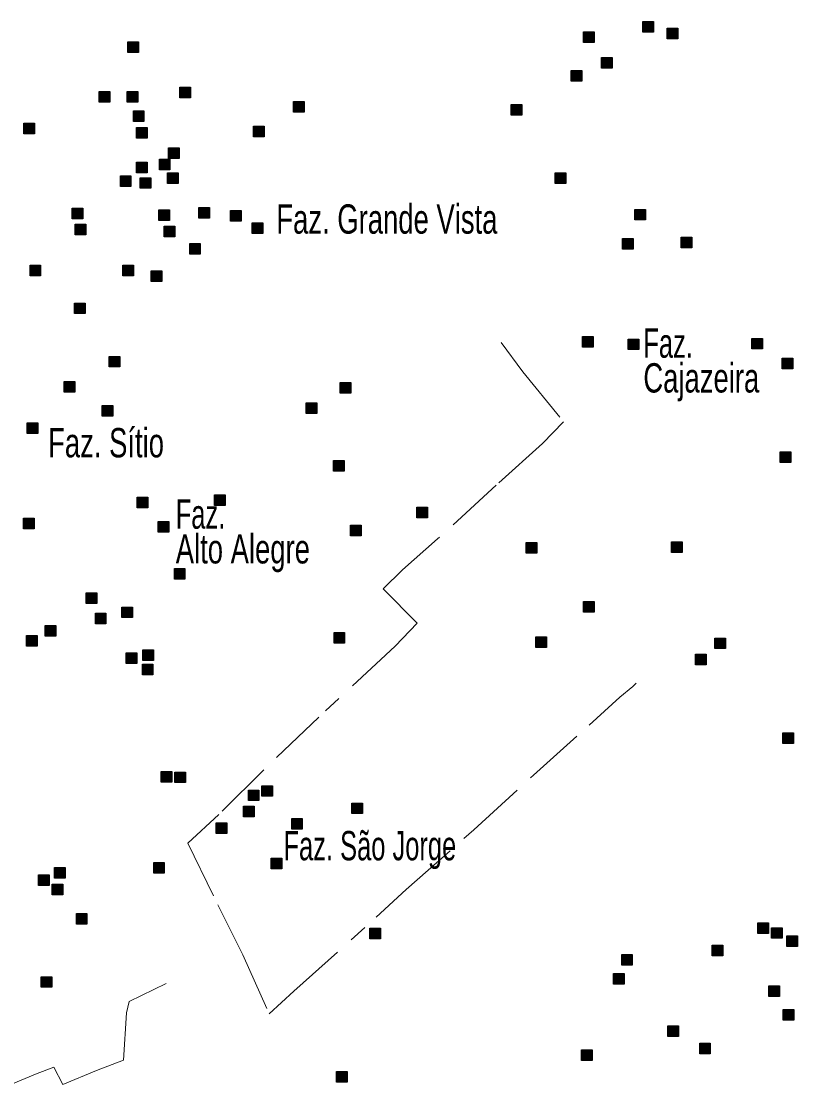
# Model space of a CAD drawing. Extents: x 445.6 to 500, y 8618.1 to 8673.4.
# Drawn here: x 495.76 to 499.99, y 8644.26 to 8650.11 of the extents above; entities that cross this region are included whole.
import ezdxf
from ezdxf.enums import TextEntityAlignment as Align

# ---------------------------------------------------------------- set-up
doc = ezdxf.new("R2010")
doc.units = 0
doc.header["$LTSCALE"] = 0.064
doc.linetypes.add('DOT_DASHED', pattern=[7.7, 5, -1.2, 0.3, -1.2])
doc.layers.add('2', color=7, linetype='Continuous', lineweight=25)
doc.layers.add('22', color=7, linetype='DOT_DASHED', lineweight=13)
doc.layers.add('61', color=7, linetype='Continuous')

msp = doc.modelspace()

# ---------------------------------------------------------------- hatches: boundary and pattern name
at = {"layer": '2'}
for points in [[(499.1475, 8650.1089), (499.2055, 8650.1089), (499.2055, 8650.0509), (499.1475, 8650.0509)], [(498.8232, 8650.0513), (498.8812, 8650.0513), (498.8812, 8649.9933), (498.8232, 8649.9933)], [(499.2792, 8650.0716), (499.3372, 8650.0716), (499.3372, 8650.0136), (499.2792, 8650.0136)], [(496.3356, 8649.9972), (496.3936, 8649.9972), (496.3936, 8649.9392), (496.3356, 8649.9392)], [(498.9211, 8649.9124), (498.9791, 8649.9124), (498.9791, 8649.8544), (498.9211, 8649.8544)], [(498.7556, 8649.8412), (498.8136, 8649.8412), (498.8136, 8649.7832), (498.7556, 8649.7832)], [(496.1802, 8649.7262), (496.2382, 8649.7262), (496.2382, 8649.6682), (496.1802, 8649.6682)], [(496.3322, 8649.7262), (496.3902, 8649.7262), (496.3902, 8649.6682), (496.3322, 8649.6682)], [(496.6194, 8649.7499), (496.6774, 8649.7499), (496.6774, 8649.6919), (496.6194, 8649.6919)], [(497.2409, 8649.672), (497.2989, 8649.672), (497.2989, 8649.614), (497.2409, 8649.614)], [(498.428, 8649.6549), (498.486, 8649.6549), (498.486, 8649.5969), (498.428, 8649.5969)], [(496.366, 8649.6211), (496.424, 8649.6211), (496.424, 8649.5631), (496.366, 8649.5631)], [(495.7681, 8649.5534), (495.8261, 8649.5534), (495.8261, 8649.4954), (495.7681, 8649.4954)], [(496.3829, 8649.5297), (496.4409, 8649.5297), (496.4409, 8649.4717), (496.3829, 8649.4717)], [(497.0213, 8649.5364), (497.0793, 8649.5364), (497.0793, 8649.4784), (497.0213, 8649.4784)], [(496.5586, 8649.4178), (496.6166, 8649.4178), (496.6166, 8649.3598), (496.5586, 8649.3598)], [(496.5079, 8649.3569), (496.5659, 8649.3569), (496.5659, 8649.2989), (496.5079, 8649.2989)], [(496.3829, 8649.3399), (496.4409, 8649.3399), (496.4409, 8649.2819), (496.3829, 8649.2819)], [(496.2951, 8649.2654), (496.3531, 8649.2654), (496.3531, 8649.2074), (496.2951, 8649.2074)], [(496.4032, 8649.2552), (496.4612, 8649.2552), (496.4612, 8649.1972), (496.4032, 8649.1972)], [(496.5518, 8649.2823), (496.6098, 8649.2823), (496.6098, 8649.2243), (496.5518, 8649.2243)], [(498.6678, 8649.2822), (498.7258, 8649.2822), (498.7258, 8649.2242), (498.6678, 8649.2242)], [(496.0316, 8649.0892), (496.0896, 8649.0892), (496.0896, 8649.0312), (496.0316, 8649.0312)], [(496.5045, 8649.079), (496.5625, 8649.079), (496.5625, 8649.021), (496.5045, 8649.021)], [(496.7241, 8649.0926), (496.7821, 8649.0926), (496.7821, 8649.0346), (496.7241, 8649.0346)], [(496.8958, 8649.0756), (496.9538, 8649.0756), (496.9538, 8649.0176), (496.8958, 8649.0176)], [(499.1035, 8649.0823), (499.1615, 8649.0823), (499.1615, 8649.0243), (499.1035, 8649.0243)], [(496.0485, 8649.0011), (496.1065, 8649.0011), (496.1065, 8648.9431), (496.0485, 8648.9431)], [(497.0146, 8649.0079), (497.0726, 8649.0079), (497.0726, 8648.9499), (497.0146, 8648.9499)], [(496.5349, 8648.991), (496.5929, 8648.991), (496.5929, 8648.933), (496.5349, 8648.933)], [(496.6734, 8648.8961), (496.7314, 8648.8961), (496.7314, 8648.8381), (496.6734, 8648.8381)], [(499.036, 8648.9231), (499.094, 8648.9231), (499.094, 8648.8651), (499.036, 8648.8651)], [(499.3569, 8648.9299), (499.4149, 8648.9299), (499.4149, 8648.8719), (499.3569, 8648.8719)], [(495.8019, 8648.7775), (495.8599, 8648.7775), (495.8599, 8648.7195), (495.8019, 8648.7195)], [(496.3086, 8648.7775), (496.3666, 8648.7775), (496.3666, 8648.7195), (496.3086, 8648.7195)], [(496.464, 8648.747), (496.522, 8648.747), (496.522, 8648.689), (496.464, 8648.689)], [(496.0451, 8648.5708), (496.1031, 8648.5708), (496.1031, 8648.5128), (496.0451, 8648.5128)], [(498.8172, 8648.3876), (498.8752, 8648.3876), (498.8752, 8648.3296), (498.8172, 8648.3296)], [(499.0664, 8648.3742), (499.1244, 8648.3742), (499.1244, 8648.3162), (499.0664, 8648.3162)], [(499.7419, 8648.3776), (499.7999, 8648.3776), (499.7999, 8648.3196), (499.7419, 8648.3196)], [(496.2343, 8648.2795), (496.2923, 8648.2795), (496.2923, 8648.2215), (496.2343, 8648.2215)], [(499.9075, 8648.2692), (499.9655, 8648.2692), (499.9655, 8648.2112), (499.9075, 8648.2112)], [(495.9887, 8648.1416), (496.0467, 8648.1416), (496.0467, 8648.0836), (495.9887, 8648.0836)], [(497.4951, 8648.1366), (497.5531, 8648.1366), (497.5531, 8648.0786), (497.4951, 8648.0786)], [(496.1956, 8648.0114), (496.2536, 8648.0114), (496.2536, 8647.9534), (496.1956, 8647.9534)], [(497.3093, 8648.0248), (497.3673, 8648.0248), (497.3673, 8647.9668), (497.3093, 8647.9668)], [(495.7869, 8647.9165), (495.8449, 8647.9165), (495.8449, 8647.8585), (495.7869, 8647.8585)], [(497.4579, 8647.7098), (497.5159, 8647.7098), (497.5159, 8647.6518), (497.4579, 8647.6518)], [(499.8969, 8647.7573), (499.9549, 8647.7573), (499.9549, 8647.6993), (499.8969, 8647.6993)], [(496.3872, 8647.5099), (496.4452, 8647.5099), (496.4452, 8647.4519), (496.3872, 8647.4519)], [(496.8085, 8647.5225), (496.8665, 8647.5225), (496.8665, 8647.4645), (496.8085, 8647.4645)], [(497.9133, 8647.4555), (497.9713, 8647.4555), (497.9713, 8647.3975), (497.9133, 8647.3975)], [(495.7667, 8647.3947), (495.8247, 8647.3947), (495.8247, 8647.3367), (495.7667, 8647.3367)], [(496.502, 8647.3777), (496.56, 8647.3777), (496.56, 8647.3197), (496.502, 8647.3197)], [(497.5518, 8647.3573), (497.6098, 8647.3573), (497.6098, 8647.2993), (497.5518, 8647.2993)], [(498.5094, 8647.2627), (498.5674, 8647.2627), (498.5674, 8647.2047), (498.5094, 8647.2047)], [(499.3032, 8647.2661), (499.3612, 8647.2661), (499.3612, 8647.2081), (499.3032, 8647.2081)], [(496.5898, 8647.1202), (496.6478, 8647.1202), (496.6478, 8647.0622), (496.5898, 8647.0622)], [(496.1078, 8646.9882), (496.1658, 8646.9882), (496.1658, 8646.9302), (496.1078, 8646.9302)], [(496.3037, 8646.9103), (496.3617, 8646.9103), (496.3617, 8646.8523), (496.3037, 8646.8523)], [(498.8235, 8646.9408), (498.8815, 8646.9408), (498.8815, 8646.8828), (498.8235, 8646.8828)], [(496.1585, 8646.8764), (496.2165, 8646.8764), (496.2165, 8646.8184), (496.1585, 8646.8184)], [(495.8849, 8646.8086), (495.9429, 8646.8086), (495.9429, 8646.7506), (495.8849, 8646.7506)], [(497.4613, 8646.7713), (497.5193, 8646.7713), (497.5193, 8646.7133), (497.4613, 8646.7133)], [(495.7836, 8646.7544), (495.8416, 8646.7544), (495.8416, 8646.6964), (495.7836, 8646.6964)], [(498.5634, 8646.7477), (498.6214, 8646.7477), (498.6214, 8646.6897), (498.5634, 8646.6897)], [(499.5396, 8646.7409), (499.5976, 8646.7409), (499.5976, 8646.6829), (499.5396, 8646.6829)], [(496.3274, 8646.6595), (496.3854, 8646.6595), (496.3854, 8646.6015), (496.3274, 8646.6015)], [(496.4186, 8646.6765), (496.4766, 8646.6765), (496.4766, 8646.6185), (496.4186, 8646.6185)], [(499.4349, 8646.6529), (499.4929, 8646.6529), (499.4929, 8646.5949), (499.4349, 8646.5949)], [(496.4152, 8646.5986), (496.4732, 8646.5986), (496.4732, 8646.5406), (496.4152, 8646.5406)], [(499.9104, 8646.2226), (499.9684, 8646.2226), (499.9684, 8646.1646), (499.9104, 8646.1646)], [(496.5175, 8646.0123), (496.5755, 8646.0123), (496.5755, 8645.9543), (496.5175, 8645.9543)], [(496.5918, 8646.0089), (496.6498, 8646.0089), (496.6498, 8645.9509), (496.5918, 8645.9509)], [(496.9938, 8645.9106), (497.0518, 8645.9106), (497.0518, 8645.8526), (496.9938, 8645.8526)], [(497.0681, 8645.9343), (497.1261, 8645.9343), (497.1261, 8645.8763), (497.0681, 8645.8763)], [(497.5582, 8645.8395), (497.6162, 8645.8395), (497.6162, 8645.7815), (497.5582, 8645.7815)], [(496.9668, 8645.8225), (497.0248, 8645.8225), (497.0248, 8645.7645), (496.9668, 8645.7645)], [(496.8181, 8645.7311), (496.8761, 8645.7311), (496.8761, 8645.6731), (496.8181, 8645.6731)], [(497.2302, 8645.7548), (497.2882, 8645.7548), (497.2882, 8645.6968), (497.2302, 8645.6968)], [(495.9365, 8645.4871), (495.9945, 8645.4871), (495.9945, 8645.4291), (495.9365, 8645.4291)], [(496.477, 8645.5142), (496.535, 8645.5142), (496.535, 8645.4562), (496.477, 8645.4562)], [(497.1188, 8645.538), (497.1768, 8645.538), (497.1768, 8645.48), (497.1188, 8645.48)], [(495.8487, 8645.4465), (495.9067, 8645.4465), (495.9067, 8645.3885), (495.8487, 8645.3885)], [(495.923, 8645.3957), (495.981, 8645.3957), (495.981, 8645.3377), (495.923, 8645.3377)], [(496.0548, 8645.2364), (496.1128, 8645.2364), (496.1128, 8645.1784), (496.0548, 8645.1784)], [(497.6568, 8645.1551), (497.7148, 8645.1551), (497.7148, 8645.0971), (497.6568, 8645.0971)], [(499.7746, 8645.1856), (499.8326, 8645.1856), (499.8326, 8645.1276), (499.7746, 8645.1276)], [(499.8489, 8645.1585), (499.9069, 8645.1585), (499.9069, 8645.1005), (499.8489, 8645.1005)], [(499.9334, 8645.1145), (499.9914, 8645.1145), (499.9914, 8645.0565), (499.9334, 8645.0565)], [(499.0315, 8645.0128), (499.0895, 8645.0128), (499.0895, 8644.9548), (499.0315, 8644.9548)], [(499.5247, 8645.0637), (499.5827, 8645.0637), (499.5827, 8645.0057), (499.5247, 8645.0057)], [(498.9876, 8644.9078), (499.0456, 8644.9078), (499.0456, 8644.8498), (498.9876, 8644.8498)], [(495.8622, 8644.8909), (495.9202, 8644.8909), (495.9202, 8644.8329), (495.8622, 8644.8329)], [(499.8349, 8644.8402), (499.8929, 8644.8402), (499.8929, 8644.7822), (499.8349, 8644.7822)], [(499.9127, 8644.7113), (499.9707, 8644.7113), (499.9707, 8644.6533), (499.9127, 8644.6533)], [(499.2837, 8644.6231), (499.3417, 8644.6231), (499.3417, 8644.5651), (499.2837, 8644.5651)], [(498.812, 8644.4911), (498.87, 8644.4911), (498.87, 8644.4331), (498.812, 8644.4331)], [(499.4571, 8644.5284), (499.5151, 8644.5284), (499.5151, 8644.4704), (499.4571, 8644.4704)], [(497.4744, 8644.3725), (497.5324, 8644.3725), (497.5324, 8644.3145), (497.4744, 8644.3145)]]:
    msp.add_hatch(color=256, dxfattribs=at).paths.add_polyline_path(points)

# ---------------------------------------------------------------- linework, layer by layer
for points in [[(499.1475, 8650.1089), (499.2055, 8650.1089), (499.2055, 8650.0509), (499.1475, 8650.0509)], [(498.8232, 8650.0513), (498.8812, 8650.0513), (498.8812, 8649.9933), (498.8232, 8649.9933)], [(499.2792, 8650.0716), (499.3372, 8650.0716), (499.3372, 8650.0136), (499.2792, 8650.0136)], [(496.3356, 8649.9972), (496.3936, 8649.9972), (496.3936, 8649.9392), (496.3356, 8649.9392)], [(498.9211, 8649.9124), (498.9791, 8649.9124), (498.9791, 8649.8544), (498.9211, 8649.8544)], [(498.7556, 8649.8412), (498.8136, 8649.8412), (498.8136, 8649.7832), (498.7556, 8649.7832)], [(496.1802, 8649.7262), (496.2382, 8649.7262), (496.2382, 8649.6682), (496.1802, 8649.6682)], [(496.3322, 8649.7262), (496.3902, 8649.7262), (496.3902, 8649.6682), (496.3322, 8649.6682)], [(496.6194, 8649.7499), (496.6774, 8649.7499), (496.6774, 8649.6919), (496.6194, 8649.6919)], [(497.2409, 8649.672), (497.2989, 8649.672), (497.2989, 8649.614), (497.2409, 8649.614)], [(498.428, 8649.6549), (498.486, 8649.6549), (498.486, 8649.5969), (498.428, 8649.5969)], [(496.366, 8649.6211), (496.424, 8649.6211), (496.424, 8649.5631), (496.366, 8649.5631)], [(495.7681, 8649.5534), (495.8261, 8649.5534), (495.8261, 8649.4954), (495.7681, 8649.4954)], [(496.3829, 8649.5297), (496.4409, 8649.5297), (496.4409, 8649.4717), (496.3829, 8649.4717)], [(497.0213, 8649.5364), (497.0793, 8649.5364), (497.0793, 8649.4784), (497.0213, 8649.4784)], [(496.5586, 8649.4178), (496.6166, 8649.4178), (496.6166, 8649.3598), (496.5586, 8649.3598)], [(496.5079, 8649.3569), (496.5659, 8649.3569), (496.5659, 8649.2989), (496.5079, 8649.2989)], [(496.3829, 8649.3399), (496.4409, 8649.3399), (496.4409, 8649.2819), (496.3829, 8649.2819)], [(496.2951, 8649.2654), (496.3531, 8649.2654), (496.3531, 8649.2074), (496.2951, 8649.2074)], [(496.4032, 8649.2552), (496.4612, 8649.2552), (496.4612, 8649.1972), (496.4032, 8649.1972)], [(496.5518, 8649.2823), (496.6098, 8649.2823), (496.6098, 8649.2243), (496.5518, 8649.2243)], [(498.6678, 8649.2822), (498.7258, 8649.2822), (498.7258, 8649.2242), (498.6678, 8649.2242)], [(496.0316, 8649.0892), (496.0896, 8649.0892), (496.0896, 8649.0312), (496.0316, 8649.0312)], [(496.5045, 8649.079), (496.5625, 8649.079), (496.5625, 8649.021), (496.5045, 8649.021)], [(496.7241, 8649.0926), (496.7821, 8649.0926), (496.7821, 8649.0346), (496.7241, 8649.0346)], [(496.8958, 8649.0756), (496.9538, 8649.0756), (496.9538, 8649.0176), (496.8958, 8649.0176)], [(499.1035, 8649.0823), (499.1615, 8649.0823), (499.1615, 8649.0243), (499.1035, 8649.0243)], [(496.0485, 8649.0011), (496.1065, 8649.0011), (496.1065, 8648.9431), (496.0485, 8648.9431)], [(497.0146, 8649.0079), (497.0726, 8649.0079), (497.0726, 8648.9499), (497.0146, 8648.9499)], [(496.5349, 8648.991), (496.5929, 8648.991), (496.5929, 8648.933), (496.5349, 8648.933)], [(496.6734, 8648.8961), (496.7314, 8648.8961), (496.7314, 8648.8381), (496.6734, 8648.8381)], [(499.036, 8648.9231), (499.094, 8648.9231), (499.094, 8648.8651), (499.036, 8648.8651)], [(499.3569, 8648.9299), (499.4149, 8648.9299), (499.4149, 8648.8719), (499.3569, 8648.8719)], [(495.8019, 8648.7775), (495.8599, 8648.7775), (495.8599, 8648.7195), (495.8019, 8648.7195)], [(496.3086, 8648.7775), (496.3666, 8648.7775), (496.3666, 8648.7195), (496.3086, 8648.7195)], [(496.464, 8648.747), (496.522, 8648.747), (496.522, 8648.689), (496.464, 8648.689)], [(496.0451, 8648.5708), (496.1031, 8648.5708), (496.1031, 8648.5128), (496.0451, 8648.5128)], [(498.8172, 8648.3876), (498.8752, 8648.3876), (498.8752, 8648.3296), (498.8172, 8648.3296)], [(499.0664, 8648.3742), (499.1244, 8648.3742), (499.1244, 8648.3162), (499.0664, 8648.3162)], [(499.7419, 8648.3776), (499.7999, 8648.3776), (499.7999, 8648.3196), (499.7419, 8648.3196)], [(496.2343, 8648.2795), (496.2923, 8648.2795), (496.2923, 8648.2215), (496.2343, 8648.2215)], [(499.9075, 8648.2692), (499.9655, 8648.2692), (499.9655, 8648.2112), (499.9075, 8648.2112)], [(495.9887, 8648.1416), (496.0467, 8648.1416), (496.0467, 8648.0836), (495.9887, 8648.0836)], [(497.4951, 8648.1366), (497.5531, 8648.1366), (497.5531, 8648.0786), (497.4951, 8648.0786)], [(496.1956, 8648.0114), (496.2536, 8648.0114), (496.2536, 8647.9534), (496.1956, 8647.9534)], [(497.3093, 8648.0248), (497.3673, 8648.0248), (497.3673, 8647.9668), (497.3093, 8647.9668)], [(495.7869, 8647.9165), (495.8449, 8647.9165), (495.8449, 8647.8585), (495.7869, 8647.8585)], [(497.4579, 8647.7098), (497.5159, 8647.7098), (497.5159, 8647.6518), (497.4579, 8647.6518)], [(499.8969, 8647.7573), (499.9549, 8647.7573), (499.9549, 8647.6993), (499.8969, 8647.6993)], [(496.3872, 8647.5099), (496.4452, 8647.5099), (496.4452, 8647.4519), (496.3872, 8647.4519)], [(496.8085, 8647.5225), (496.8665, 8647.5225), (496.8665, 8647.4645), (496.8085, 8647.4645)], [(497.9133, 8647.4555), (497.9713, 8647.4555), (497.9713, 8647.3975), (497.9133, 8647.3975)], [(495.7667, 8647.3947), (495.8247, 8647.3947), (495.8247, 8647.3367), (495.7667, 8647.3367)], [(496.502, 8647.3777), (496.56, 8647.3777), (496.56, 8647.3197), (496.502, 8647.3197)], [(497.5518, 8647.3573), (497.6098, 8647.3573), (497.6098, 8647.2993), (497.5518, 8647.2993)], [(498.5094, 8647.2627), (498.5674, 8647.2627), (498.5674, 8647.2047), (498.5094, 8647.2047)], [(499.3032, 8647.2661), (499.3612, 8647.2661), (499.3612, 8647.2081), (499.3032, 8647.2081)], [(496.5898, 8647.1202), (496.6478, 8647.1202), (496.6478, 8647.0622), (496.5898, 8647.0622)], [(496.1078, 8646.9882), (496.1658, 8646.9882), (496.1658, 8646.9302), (496.1078, 8646.9302)], [(496.3037, 8646.9103), (496.3617, 8646.9103), (496.3617, 8646.8523), (496.3037, 8646.8523)], [(498.8235, 8646.9408), (498.8815, 8646.9408), (498.8815, 8646.8828), (498.8235, 8646.8828)], [(496.1585, 8646.8764), (496.2165, 8646.8764), (496.2165, 8646.8184), (496.1585, 8646.8184)], [(495.8849, 8646.8086), (495.9429, 8646.8086), (495.9429, 8646.7506), (495.8849, 8646.7506)], [(497.4613, 8646.7713), (497.5193, 8646.7713), (497.5193, 8646.7133), (497.4613, 8646.7133)], [(495.7836, 8646.7544), (495.8416, 8646.7544), (495.8416, 8646.6964), (495.7836, 8646.6964)], [(498.5634, 8646.7477), (498.6214, 8646.7477), (498.6214, 8646.6897), (498.5634, 8646.6897)], [(499.5396, 8646.7409), (499.5976, 8646.7409), (499.5976, 8646.6829), (499.5396, 8646.6829)], [(496.3274, 8646.6595), (496.3854, 8646.6595), (496.3854, 8646.6015), (496.3274, 8646.6015)], [(496.4186, 8646.6765), (496.4766, 8646.6765), (496.4766, 8646.6185), (496.4186, 8646.6185)], [(499.4349, 8646.6529), (499.4929, 8646.6529), (499.4929, 8646.5949), (499.4349, 8646.5949)], [(496.4152, 8646.5986), (496.4732, 8646.5986), (496.4732, 8646.5406), (496.4152, 8646.5406)], [(499.9104, 8646.2226), (499.9684, 8646.2226), (499.9684, 8646.1646), (499.9104, 8646.1646)], [(496.5175, 8646.0123), (496.5755, 8646.0123), (496.5755, 8645.9543), (496.5175, 8645.9543)], [(496.5918, 8646.0089), (496.6498, 8646.0089), (496.6498, 8645.9509), (496.5918, 8645.9509)], [(496.9938, 8645.9106), (497.0518, 8645.9106), (497.0518, 8645.8526), (496.9938, 8645.8526)], [(497.0681, 8645.9343), (497.1261, 8645.9343), (497.1261, 8645.8763), (497.0681, 8645.8763)], [(497.5582, 8645.8395), (497.6162, 8645.8395), (497.6162, 8645.7815), (497.5582, 8645.7815)], [(496.9668, 8645.8225), (497.0248, 8645.8225), (497.0248, 8645.7645), (496.9668, 8645.7645)], [(496.8181, 8645.7311), (496.8761, 8645.7311), (496.8761, 8645.6731), (496.8181, 8645.6731)], [(497.2302, 8645.7548), (497.2882, 8645.7548), (497.2882, 8645.6968), (497.2302, 8645.6968)], [(495.9365, 8645.4871), (495.9945, 8645.4871), (495.9945, 8645.4291), (495.9365, 8645.4291)], [(496.477, 8645.5142), (496.535, 8645.5142), (496.535, 8645.4562), (496.477, 8645.4562)], [(497.1188, 8645.538), (497.1768, 8645.538), (497.1768, 8645.48), (497.1188, 8645.48)], [(495.8487, 8645.4465), (495.9067, 8645.4465), (495.9067, 8645.3885), (495.8487, 8645.3885)], [(495.923, 8645.3957), (495.981, 8645.3957), (495.981, 8645.3377), (495.923, 8645.3377)], [(496.0548, 8645.2364), (496.1128, 8645.2364), (496.1128, 8645.1784), (496.0548, 8645.1784)], [(497.6568, 8645.1551), (497.7148, 8645.1551), (497.7148, 8645.0971), (497.6568, 8645.0971)], [(499.7746, 8645.1856), (499.8326, 8645.1856), (499.8326, 8645.1276), (499.7746, 8645.1276)], [(499.8489, 8645.1585), (499.9069, 8645.1585), (499.9069, 8645.1005), (499.8489, 8645.1005)], [(499.9334, 8645.1145), (499.9914, 8645.1145), (499.9914, 8645.0565), (499.9334, 8645.0565)], [(499.0315, 8645.0128), (499.0895, 8645.0128), (499.0895, 8644.9548), (499.0315, 8644.9548)], [(499.5247, 8645.0637), (499.5827, 8645.0637), (499.5827, 8645.0057), (499.5247, 8645.0057)], [(498.9876, 8644.9078), (499.0456, 8644.9078), (499.0456, 8644.8498), (498.9876, 8644.8498)], [(495.8622, 8644.8909), (495.9202, 8644.8909), (495.9202, 8644.8329), (495.8622, 8644.8329)], [(499.8349, 8644.8402), (499.8929, 8644.8402), (499.8929, 8644.7822), (499.8349, 8644.7822)], [(499.9127, 8644.7113), (499.9707, 8644.7113), (499.9707, 8644.6533), (499.9127, 8644.6533)], [(499.2837, 8644.6231), (499.3417, 8644.6231), (499.3417, 8644.5651), (499.2837, 8644.5651)], [(498.812, 8644.4911), (498.87, 8644.4911), (498.87, 8644.4331), (498.812, 8644.4331)], [(499.4571, 8644.5284), (499.5151, 8644.5284), (499.5151, 8644.4704), (499.4571, 8644.4704)], [(497.4744, 8644.3725), (497.5324, 8644.3725), (497.5324, 8644.3145), (497.4744, 8644.3145)]]:
    msp.add_lwpolyline(points, close=True, dxfattribs=at)
at = {"layer": '22'}
for points in [[(498.3734, 8648.3558), (498.4925, 8648.1953), (498.7143, 8647.9222), (498.5988, 8647.8038), (498.3466, 8647.5762), (498.0267, 8647.2827), (497.8353, 8647.1127), (497.7289, 8647.0095), (497.9143, 8646.8214), (497.7957, 8646.6969), (497.3789, 8646.3088), (497.078, 8646.0205), (496.8318, 8645.7777), (496.6634, 8645.6206), (496.8276, 8645.2838), (496.9643, 8645.0106), (497.1078, 8644.6872), (497.2416, 8644.8116), (497.6914, 8645.2153), (497.8555, 8645.367), (498.2241, 8645.6935), (498.5493, 8645.991), (498.8542, 8646.2657), (499.0214, 8646.4175), (499.0918, 8646.4764), (499.1098, 8646.4942)], [(493.6445, 8643.3918), (493.8716, 8643.4873), (494.221, 8643.6481), (494.8065, 8643.9112), (495.1232, 8644.042), (495.3497, 8644.1429), (495.6973, 8644.3019), (495.8311, 8644.3592), (495.9321, 8644.3973), (495.9812, 8644.3019), (496.1641, 8644.3783), (496.3115, 8644.4355), (496.3279, 8644.6944), (496.3423, 8644.756), (496.5443, 8644.8541)]]:
    msp.add_lwpolyline(points, dxfattribs=at)

# ---------------------------------------------------------------- texts
at = {"layer": '61'}
for s, width, p in [('Faz. Grande Vista', 0.7, (497.1463, 8648.9496)), ('Faz.', 0.65, (499.1496, 8648.2719)), ('Cajazeira', 0.7, (499.1496, 8648.0819)), ('Faz.', 0.65, (496.5973, 8647.3381)), ('Alto Alegre', 0.7, (496.5973, 8647.1481)), ('Faz. São Jorge', 0.65, (497.1853, 8645.5267))]:
    msp.add_text(s, height=0.16, dxfattribs=dict(at, width=width)).set_placement(p)
at = {"layer": '61', "width": 0.7}
msp.add_text('Faz. Sítio', height=0.16, dxfattribs=at).set_placement((496.217, 8647.7277), align=Align.CENTER)

doc.saveas('drawing.dxf')
